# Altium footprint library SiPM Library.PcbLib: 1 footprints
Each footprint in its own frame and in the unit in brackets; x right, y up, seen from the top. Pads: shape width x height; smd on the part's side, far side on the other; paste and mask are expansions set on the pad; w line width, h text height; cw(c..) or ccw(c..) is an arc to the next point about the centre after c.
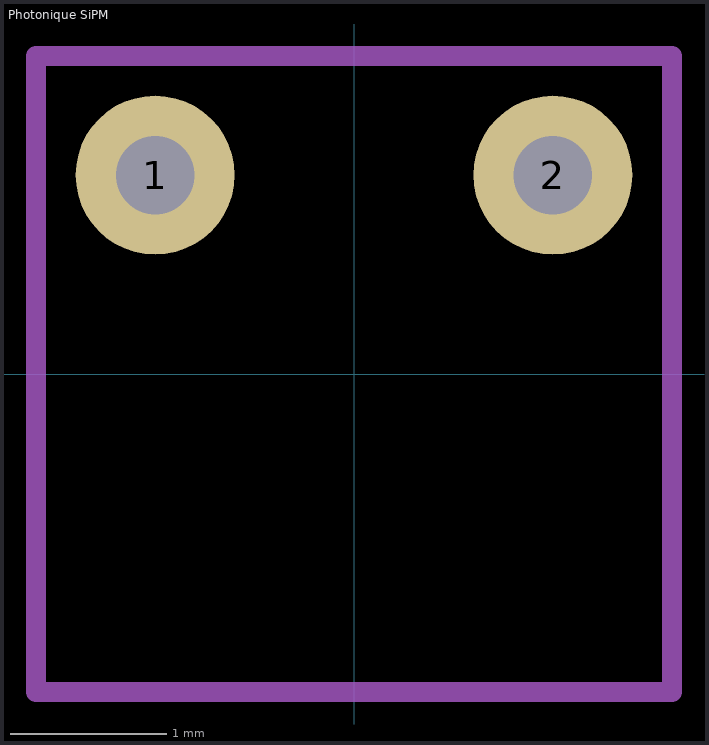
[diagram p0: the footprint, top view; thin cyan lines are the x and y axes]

## Photonique SiPM [mil]
pads (2):
  round 40 hole 19.7: 1(-50,50) 2(50,50)
Mechanical 1:
  lines w5: -80,-80 80,-80 80,80 -80,80 -80,-80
